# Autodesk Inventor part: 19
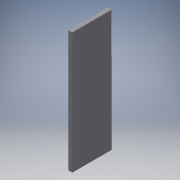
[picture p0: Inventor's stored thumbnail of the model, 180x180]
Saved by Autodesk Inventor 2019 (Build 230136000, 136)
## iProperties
Created: 2019-01
Part Number: 19
Material: Generic
Document SubType Name: Modeling
Designer: Guy Link
Density: 1 g/cm^3
Appearance: Default
Author: Guy Link
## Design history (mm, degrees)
sketch "Sketch1"
  geometry: L1 (65.929, 16.883)-(66.036, -14.856); L2 (66.036, -14.856)-(-32.423, -15.006); L3 (-32.423, -15.006)-(-32.462, 16.883); L4 (-32.462, 16.883)-(65.929, 16.883); 1 further point
  constraints: 8 end point
extrude "Extrusion1" new body sketch "Sketch1" distance "d0" = 3.175; taper "d1" = 0 deg
body "Solid1"
